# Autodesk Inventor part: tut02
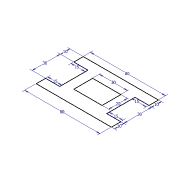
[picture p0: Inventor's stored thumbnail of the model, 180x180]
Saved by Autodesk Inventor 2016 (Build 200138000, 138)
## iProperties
Created: 2015-02
Part Number: tut02
Material: Generic
Document SubType Name: Modeling
Designer: Sandeep
Density: 1 g/cm^3
Appearance: Default
Author: Sandeep
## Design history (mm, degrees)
sketch "Sketch1"
  geometry: L1 (-40, -25)-(40, -25); L2 (40, -25)-(40, -15); L3 (40, -15)-(25, -15); L4 (25, -15)-(25, 15); L5 (25, 15)-(40, 15); L6 (40, 15)-(40, 25); L7 (40, 25)-(-40, 25); L8 (-40, 25)-(-40, 15); L9 (-40, 15)-(-25, 15); L10 (-25, 15)-(-25, -15); L11 (-25, -15)-(-40, -15); L12 (-40, -15)-(-40, -25); L13 (-15, -10)-(15, -10); L14 (15, -10)-(15, 10); L15 (15, 10)-(-15, 10); L16 (-15, 10)-(-15, -10)
  constraints: 32 end point, 7 perpendicular, 3 horizontal, 2 parallel, 2 point on line, 1 vertical
  dimensions: "d0" = 80 distance of L1.start L1.end; "d1" = 10 distance of L1.end L2.end; "d2" = 15 distance of L2.end L3.end; "d3" = 30 distance of L3.end L4.end; "d4" = 15 distance of L4.end L5.end; "d5" = 10 distance of L5.end L6.end; "d6" = 80 distance of L6.end L7.end; "d7" = 10 distance of L7.end L8.end; "d8" = 15 distance of L8.end L9.end; "d9" = 30 distance of L9.end L10.end; "d10" = 15 distance of L10.end L11.end; "d12" = 30 distance of L15.end L14.end; "d13" = 20 distance of L14.end L13.end
